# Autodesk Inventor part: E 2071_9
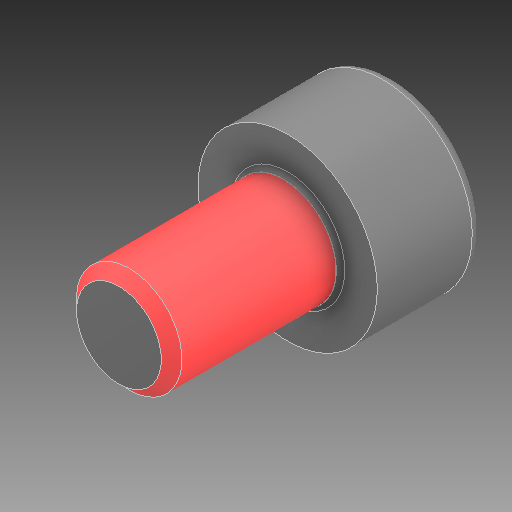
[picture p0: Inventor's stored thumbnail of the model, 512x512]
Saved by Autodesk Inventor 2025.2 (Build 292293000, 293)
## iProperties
Created: 2025-04
Part Number: E 2071_9
Material: Všeobecné
Document SubType Name: Modeling
Designer: Patrik
Density: 1 g/cm^3
Appearance: Výchozí
Mass: 0.403175 g
Surface Area: 3.95326 cm^2
Volume: 0.403175 cm^3
Author: Patrik
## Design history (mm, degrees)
feature "Base1"
node "Těleso1"
